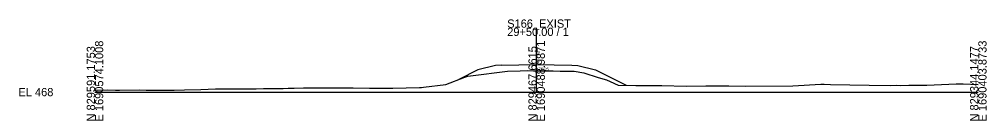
# Model space of a CAD drawing. Extents: x 1621104 to 1621433, y 1192880 to 1199414.
# Drawn here: x 1621104.2 to 1621432.7, y 1195379.5 to 1195413.9 of the extents above; entities that cross this region are included whole.
import ezdxf

# ---------------------------------------------------------------- set-up
doc = ezdxf.new("R2010")
doc.units = 0
for name, color, linetype in [('RD_GPK_XS_Cell', 7, 'Continuous'), ('RD_XS_EarthShd', 7, 'Continuous'), ('RD_XS_ExGround', 7, 'Continuous'), ('RD_XS_Pave', 7, 'Continuous'), ('RD_XS_TieSlope', 7, 'Continuous'), ('RD_XS_TX_Elev_EX', 7, 'Continuous'), ('RD_XS_TX_Elev_PR', 7, 'Continuous')]:
    doc.layers.add(name, color=color, linetype=linetype)

msp = doc.modelspace()

# ---------------------------------------------------------------- linework, layer by layer
at = {"layer": 'RD_GPK_XS_Cell'}
for p, q in [((1621279.86, 1195389.24), (1621279.86, 1195411.1)), ((1621129.86, 1195389.24), (1621279.86, 1195389.24)), ((1621279.86, 1195389.24), (1621429.86, 1195389.24))]:
    msp.add_line(p, q, dxfattribs=at)
at = {"layer": 'RD_XS_EarthShd'}
for p, q in [((1621267.86, 1195398.41), (1621265.86, 1195398.25)), ((1621291.86, 1195398.41), (1621293.86, 1195398.25))]:
    msp.add_line(p, q, dxfattribs=at)
at = {"layer": 'RD_XS_ExGround'}
msp.add_lwpolyline([(1621129.86, 1195389.97), (1621130.61, 1195389.94), (1621134.26, 1195389.96), (1621136.86, 1195389.85), (1621138.14, 1195389.91), (1621144.88, 1195389.96), (1621147.29, 1195389.91), (1621151.03, 1195389.9), (1621152.79, 1195389.86), (1621156.7, 1195389.91), (1621160.31, 1195390.01), (1621165.81, 1195390.14), (1621170.77, 1195390.31), (1621174.86, 1195390.38), (1621175.95, 1195390.4), (1621184.65, 1195390.4), (1621187.08, 1195390.45), (1621187.83, 1195390.45), (1621193.79, 1195390.49), (1621195.51, 1195390.54), (1621197.52, 1195390.59), (1621200.72, 1195390.63), (1621204.38, 1195390.69), (1621212.24, 1195390.69), (1621214.09, 1195390.67), (1621216.07, 1195390.64), (1621217.54, 1195390.71), (1621223.05, 1195390.59), (1621228.35, 1195390.53), (1621230.99, 1195390.61), (1621240.04, 1195390.79), (1621240.73, 1195390.8), (1621241.47, 1195390.91), (1621249.02, 1195391.8), (1621255.48, 1195394.35), (1621256.52, 1195394.67), (1621257.39, 1195394.75), (1621269.98, 1195396.37), (1621274.22, 1195396.48), (1621276.75, 1195396.52), (1621278.75, 1195396.5), (1621279.86, 1195396.48), (1621285.51, 1195396.41), (1621287.88, 1195396.37), (1621292.65, 1195396.32), (1621295.9, 1195395.77), (1621300.81, 1195394.16), (1621303.54, 1195393.43), (1621304.8, 1195392.85), (1621307.53, 1195391.63), (1621313.53, 1195391.5), (1621322.37, 1195391.43), (1621330.62, 1195391.22), (1621337.3, 1195391.32), (1621340.55, 1195391.34), (1621345.14, 1195391.33), (1621350.65, 1195391.3), (1621366.89, 1195391.38), (1621376.42, 1195391.9), (1621377.54, 1195391.92), (1621379.62, 1195391.85), (1621392.76, 1195391.58), (1621399.91, 1195391.53), (1621401.91, 1195391.55), (1621403.37, 1195391.53), (1621406.32, 1195391.58), (1621412.34, 1195391.62), (1621422.32, 1195392.06), (1621422.94, 1195392.1), (1621424.71, 1195392.07), (1621429.86, 1195391.78)], dxfattribs=at)
at = {"layer": 'RD_XS_Pave'}
for p, q in [((1621267.86, 1195398.41), (1621279.86, 1195398.65)), ((1621279.86, 1195398.65), (1621291.86, 1195398.41))]:
    msp.add_line(p, q, dxfattribs=at)
at = {"layer": 'RD_XS_TieSlope'}
for p, q in [((1621259.86, 1195396.75), (1621253.43, 1195393.54)), ((1621265.86, 1195398.25), (1621259.86, 1195396.75)), ((1621293.86, 1195398.25), (1621299.86, 1195396.75)), ((1621299.86, 1195396.75), (1621310.22, 1195391.57))]:
    msp.add_line(p, q, dxfattribs=at)

# ---------------------------------------------------------------- texts
at = {"layer": 'RD_GPK_XS_Cell'}
for s, p in [('S166_EXIST', (1621269.86, 1195411.1)), ('29+50.00 / 1', (1621269.86, 1195408.3)), ('EL 468', (1621103.86, 1195387.84))]:
    msp.add_text(s, height=2.8, dxfattribs=at).set_placement(p)
for s, p in [('E 1690574.1008', (1621132.66, 1195379.24)), ('E 1690488.9871', (1621282.66, 1195379.24)), ('E 1690403.8733', (1621432.66, 1195379.24)), ('N 829591.1753', (1621129.86, 1195379.24)), ('N 829467.6615', (1621279.86, 1195379.24)), ('N 829344.1477', (1621429.86, 1195379.24))]:
    msp.add_text(s, height=2.8, rotation=90, dxfattribs=at).set_placement(p)
at = {"layer": 'RD_XS_TX_Elev_EX'}
msp.add_text('475.25', height=1, dxfattribs=at).set_placement((1621279.76, 1195396.58))
at = {"layer": 'RD_XS_TX_Elev_PR'}
msp.add_text(' 477.42', height=1, rotation=90, dxfattribs=at).set_placement((1621280.86, 1195398.65))

doc.saveas('drawing.dxf')
